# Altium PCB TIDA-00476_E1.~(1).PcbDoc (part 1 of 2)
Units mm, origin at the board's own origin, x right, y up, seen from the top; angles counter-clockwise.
Board outline 85.09 x 49.91 mm, 2 copper layers (Top Layer, Bottom Layer), stack 1.575 mm thick; 132 components, 75 nets, 329 pads, 292 vias.
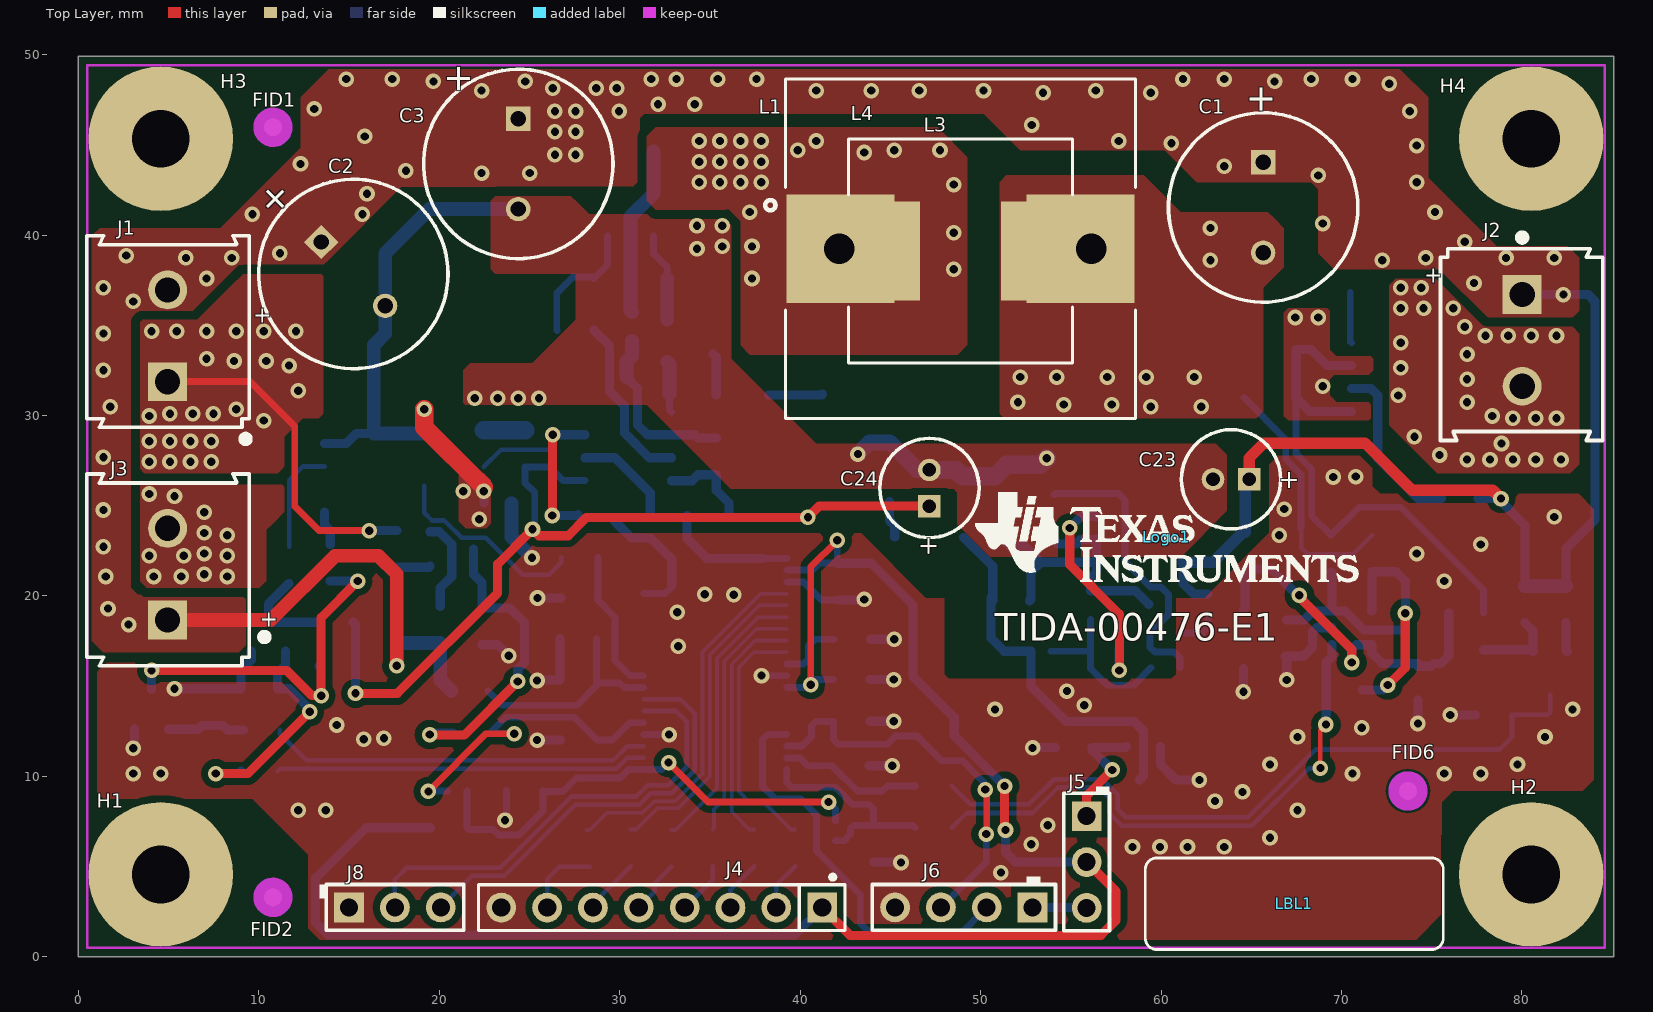
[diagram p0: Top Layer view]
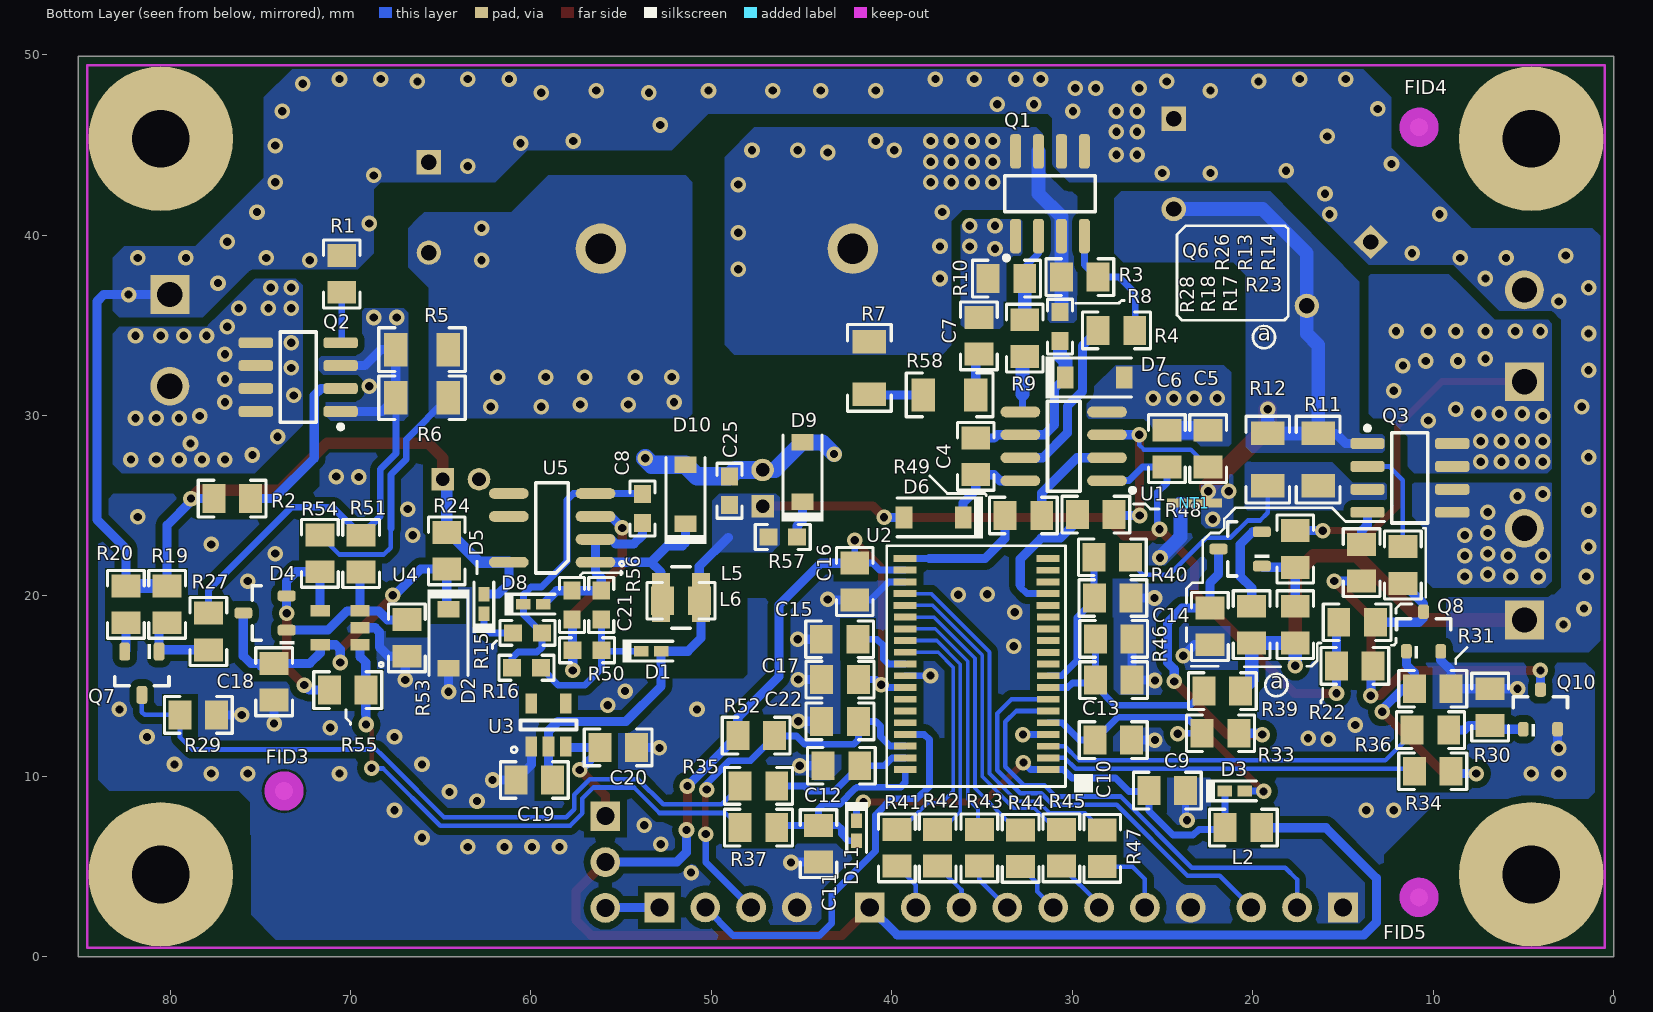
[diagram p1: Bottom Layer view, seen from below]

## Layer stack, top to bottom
Top Solder: solder mask 0.0102, Solder Resist, Dk 3.5
Top Layer: signal copper 0.0356
Dielectric1: core 1.5037, FR-4, Dk 4.8
Bottom Layer: signal copper 0.0356
Bottom Solder: solder mask 0.0102, Solder Resist, Dk 3.5

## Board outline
0,0 0,49.911 85.09,49.911 85.09,0

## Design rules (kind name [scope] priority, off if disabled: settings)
AcuteAngle [All] p1: minimum=4.50000000000000E+0001 checktracksonly=TRUE
AssemblyTestPointUsage [All] p1: valid=2
Clearance Clearance_keepout [InPolygon vs IsKeepOut] p1: gap=0.127
Clearance Clearance_poly-poly [InPolygon vs InPolygon] p2: gap=0.508
Clearance "VIA to SMD" [IsVia vs IsPad] p3: gap=0.203
Clearance Clearance_BoardEdge_MountingHoles [OnCopper and InComponentClass('Mounting Holes') vs IsKeepOut] p4: gap=1.016
Clearance Clearance_BoardEdge_Poly [OnCopper and InPoly vs IsKeepOut] p5: gap=0.508
Clearance Clearance_Poly [InPolygon] p6: gap=0.381
Clearance [All] p7: gap=0.2
ComponentClearance ComponentClearance_MountingHoles_FiducialMarks [InComponentClass('Mounting Holes') vs InComponentClass('FiducialMark')] p1: gap=1.016 collisioncheckmode=3 verticalgap=0.254 showdistances=FALSE
ComponentClearance ComponentClearance_Shunt [InComponentClass('Header') vs InComponentClass('Shunt')] p2: gap=0 collisioncheckmode=3 verticalgap=0 showdistances=FALSE
ComponentClearance ComponentClearance_Logo [InComponentClass('Logo')] p3: gap=0.889 collisioncheckmode=3 verticalgap=0.254 showdistances=FALSE
ComponentClearance ComponentClearance_ScrewToNut [(HasFootprint('NY PMS 440 0025 PH')) vs (HasFootprint('Keystone_1902C'))] p4: gap=0.127 collisioncheckmode=3 verticalgap=0.254 showdistances=FALSE
ComponentClearance ComponentClearance_MountingHoles [InComponentClass('Mounting Holes')] p5: gap=6.35 collisioncheckmode=3 verticalgap=2540 showdistances=FALSE
ComponentClearance ComponentClearance_SmallPassives [HasFootprint('0201*') or HasFootprint('0402*') or HasFootprint('0508') or HasFootprint('0603*') or HasFootprint('0612') or HasFootprint('0805*') or HasFootprint('0815*') or HasFootprint('0830*') or HasFootprint('1206*') or HasFootprint('1210*') or HasFootprint('1808*') or HasFootprint('1812*') or HasFootprint('1825*') or HasFootprint('2010*') or HasFootprint('2220*') or HasFootprint('2225*') or HasFootprint('2512*') or HasFootprint('2728*') or HasFootprint('3518*') vs HasFootprint('0201*') or HasFootprint('0402*') or HasFootprint('0508') or HasFootprint('0603*') or HasFootprint('0612') or HasFootprint('0805*') or HasFootprint('0815*') or HasFootprint('0830*') or HasFootprint('1206*') or HasFootprint('1210*') or HasFootprint('1808*') or HasFootprint('1812*') or HasFootprint('1825*') or HasFootprint('2010*') or HasFootprint('2220*') or HasFootprint('2225*') or HasFootprint('2512*') or HasFootprint('2728*') or HasFootprint('3518*')] p6: gap=0.508 collisioncheckmode=3 verticalgap=0.254 showdistances=FALSE
ComponentClearance ComponentClearance_THtoSMT [IsThruComponent vs IsSMTComponent] p7: gap=1.27 collisioncheckmode=3 verticalgap=0.762 showdistances=FALSE
ComponentClearance ComponentClearance_THtoTH [IsThruComponent vs IsThruComponent] p8: gap=3 collisioncheckmode=3 verticalgap=0.762 showdistances=FALSE
ComponentClearance [All] p9: gap=0.762 collisioncheckmode=3 verticalgap=0.254 showdistances=FALSE
DiffPairsRouting DiffPair_DP_DMDiffPairsRouting [InDifferentialPair ('MSP_DP_DM_DIFF')] p1: maxlimit=0.203 minlimit=0.203 mostfreqgap=0.203 toplayer_minwidth=0.381 toplayer_maxwidth=0.381 toplayer_prefwidth=0.381 bottomlayer_minwidth=0.381 bottomlayer_maxwidth=0.381 bottomlayer_prefwidth=0.381 maxuncoupledlength=12.7
DiffPairsRouting DiffPair_MSP_DP_DMDiffPairsRouting [InDifferentialPair ('MSP_DP_DM_DIFF')] p2: maxlimit=0.203 minlimit=0.203 mostfreqgap=0.203 toplayer_minwidth=0.381 toplayer_maxwidth=0.381 toplayer_prefwidth=0.381 bottomlayer_minwidth=0.381 bottomlayer_maxwidth=0.381 bottomlayer_prefwidth=0.381 maxuncoupledlength=12.7
DiffPairsRouting [All] p3: maxlimit=0.203 minlimit=0.203 mostfreqgap=0.203 toplayer_minwidth=0.381 toplayer_maxwidth=0.381 toplayer_prefwidth=0.381 bottomlayer_minwidth=0.381 bottomlayer_maxwidth=0.381 bottomlayer_prefwidth=0.381 maxuncoupledlength=25.4
FabricationTestPointUsage TestPointUsage [All] p1: valid=2 allowmultiple=FALSE
FabricationTestpoint Testpoint [All] p1: side=3 testpointundercomponent=TRUE minsize=1.016 maxsize=2.54 preferedsize=1.524 minholesize=0 maxholesize=1.016 preferedholesize=0.813 testpointgrid=0.025 allowsidetop=TRUE allowsidebottom=TRUE usegrid=TRUE gridtolerance=0
FanoutControl Fanout_LCC [IsLCC] p1: bgadir=Out bgaviamode=Centered fanoutstyle=Auto fanoutdirection=Alternating viagrid=0.025 // Fanout_LCC (Default Rule)
FanoutControl Fanout_BGA [IsBGA] p2: bgadir=Out bgaviamode=Centered fanoutstyle=Auto fanoutdirection=Alternating viagrid=0.025 // Fanout_BGA (Default Rule)
FanoutControl Fanout_Default [All] p4: bgadir=Out bgaviamode=Centered fanoutstyle=Auto fanoutdirection=Alternating viagrid=0.025 // Fanout_Default (Default Rule)
FanoutControl Fanout_Small [(CompPinCount < 5)] p5: bgadir=Out bgaviamode=Centered fanoutstyle=Auto fanoutdirection=OutThenIn viagrid=0.025 // Fanout_Small (Default Rule)
HoleSize [All] p1: absolutevalues=TRUE maxlimit=6.375 minlimit=0.2 maxpercent=80.000 minpercent=20.000
MatchedLengths DiffPair_DP_DMMatchedLengths [InDifferentialPair ('MSP_DP_DM_DIFF')] p1: tolerance=5.08 checknetsindiffpair=TRUE checkdiffpairvsdiffpair=TRUE checkothers=TRUE
MatchedLengths DiffPair_MSP_DP_DMMatchedLengths [InDifferentialPair ('MSP_DP_DM_DIFF')] p2: tolerance=5.08 checknetsindiffpair=TRUE checkdiffpairvsdiffpair=TRUE checkothers=TRUE
MinimumAnnularRing MinimumAnnularRing_ThermalPadVias [IsVia and InAnyComponent] p1: minimumring=0.15
MinimumAnnularRing [All] p2: minimumring=0.152
MinimumSolderMaskSliver MinimumSolderMaskSliver_Logo [InComponentClass('Logo') vs InComponentClass('Logo')] p1: minsoldermaskwidth=0.018
MinimumSolderMaskSliver [All] p2: minsoldermaskwidth=0.064
PlaneConnect [All] p1: planeconnectstyle=Direct reliefexpansion=0.254 reliefentries=4 reliefconductorwidth=0.254 reliefairgap=0.254
PolygonConnect [All] p1: connectstyle=Direct reliefconductorwidth=0.254 reliefentries=4 polygonreliefangle="90 Angle" airgapwidth=0.254
RoutingVias RoutingVias_1 [All] p1: holewidth=0.305 width=0.61 viastyle="Through Hole" minholewidth=0.305 minwidth=0.61 maxholewidth=0.457 maxwidth=0.864
RoutingVias ThermalPadVias [IsVia and InAnyComponent] p2: holewidth=0.305 width=0.61 viastyle="Through Hole" minholewidth=0.2 minwidth=0.5 maxholewidth=0.406 maxwidth=0.813
RoutingVias RoutingVias_power [InNetClass('Power')] p3: holewidth=0.305 width=0.61 viastyle="Through Hole" minholewidth=0.305 minwidth=0.61 maxholewidth=0.457 maxwidth=0.864
SilkToSilkClearance SilkToSilkClearance_Pb-FreeLogo [(HasFootprint('Pb-Free_Overlay_Medium') OR HasFootprint('Pb-Free_Overlay_Small')) vs (HasFootprint('Pb-Free_Overlay_Medium') OR HasFootprint('Pb-Free_Overlay_Small'))] p1: silktosilkclearance=0
SilkToSilkClearance [All] p2: silktosilkclearance=0.127
SilkToSolderMaskClearance "Silk to Solder Mask Opening" [IsPad] p1: minsilkscreentomaskgap=0.025 clearancetoexposedcopper=TRUE
SolderMaskExpansion [All] p1: expansion=0.064
UnpouredPolygon [All] p1: allowunpoured=FALSE
Width Width_PWR [InNetClass('Power')] p1: maxlimit=2.54 minlimit=0.203 preferedwidth=0.508
Width [All] p2: maxlimit=2.54 minlimit=0.203 preferedwidth=0.381 checkconnectedcopper=TRUE
15 further rules are at their usual default settings.

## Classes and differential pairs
component class TIDA-00476_Sheet2: C1 C2 C3 C4 C5 C6 C7 C8 C21 C23 C24 C25 D1 D2 D5 D6 D7 D8 D9 D10 J1 J2 J3 L1 L3 L4 L5 L6 NT1 Q1 Q2 Q3 Q6 Q7 Q8 Q10 R1 R2 R3 R4 R5 R6 R7 R8 R9 R10 R11 R12 R13 R14 R15 R16 R17 R18 R19 R20 R22 R23 R24 R26 R27 R28 R29 R30 R31 R50 R56 R57 R58 U1 U5
component class TIDA-00467_Sheet1: C9 C10 C11 C12 C13 C14 C15 C16 C17 C18 C19 C20 C22 D3 D4 D11 J4 J5 J6 J8 L2 R33 R34 R35 R36 R37 R39 R40 R41 R42 R43 R44 R45 R46 R47 R48 R49 R51 R52 R53 R54 R55 U2 U3 U4
component class Hardware: FID1 FID2 FID3 FID4 FID5 FID6 H1 H2 H3 H4 LBL1 Logo1 ZZ1 ZZ2 ZZ3 ZZ4

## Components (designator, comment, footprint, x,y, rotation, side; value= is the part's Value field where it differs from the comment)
C1 "EKYB630ELL391MJ30S" KZN_1000x2000 65.659,41.529 r270 top
C2 "EKYB630ELL391MJ30S" KZN_1000x2000 15.24,37.846 r315 top
C3 "EKYB630ELL391MJ30S" KZN_1000x2000 24.384,43.942 r270 top
C4 "08053C104KAT2A" 0805_HV#1 35.357,27.737 r90 bottom
C5 "GRM2165C2A221JA01D" 0805_HV#1 22.479,28.169 r90 bottom
C6 "08055C105KAT2A" 0805_HV#1 24.765,28.169 r90 bottom
C7 "GRM2195C2A102JA01D" 0805_HV#1 35.179,34.417 r90 bottom
C8 "C1608X5R1A106M" 0603 53.823,24.841 r270 bottom
C9 "08055C105KAT2A" 0805_HV#1 24.74,9.22 r180 bottom
C10 "08053C104KAT2A" 0805_HV#1 27.737,12.014 r180 bottom
C11 "08055C222KAT2A" 0805_HV#1 44.069,6.274 r270 bottom
C12 "08053C104KAT2A" 0805_HV#1 42.799,10.592 r0 bottom
C13 "08055C222KAT2A" 0805_HV#1 27.711,15.342 r180 bottom
C14 "08053C104KAT2A" 0805_HV#1 27.762,19.888 r180 bottom
C15 "08055C105KAT2A" 0805_HV#1 42.901,17.602 r0 bottom
C16 "08055C105KAT2A" 0805_HV#1 42.062,20.803 r270 bottom
C17 "08055C105KAT2A" 0805_HV#1 42.875,15.367 r0 bottom
C18 "08055C105KAT2A" 0805_HV#1 74.234,15.247 r270 bottom
C19 "08055C105KAT2A" 0805_HV#1 59.817,9.804 r0 bottom
C20 "08055C105KAT2A" 0805_HV#1 55.169,11.608 r180 bottom
C21 "0603YC104JAT2A" 0603 56.109,19.495 r90 bottom
C22 "08055C102KAT2A" 0805_HV#1 42.875,13.056 r0 bottom
C23 "35ZLJ47MTA5X11" ZLJ_500x1100 63.881,26.467 r180 top
C24 "16PX100MEFCTA5X11" ZLJ_500x1100 47.168,25.984 r90 top
C25 "06033C101KAT2A" 0603 48.997,25.832 r90 bottom
D1 "1N4148X-TP" SOD-523 53.34,16.942 r180 bottom
D2 "MMSZ4715-V" SOD-123 64.567,17.628 r270 bottom
D3 "BAS 52-02V H6327" SOD-523 21.006,9.195 r180 bottom
D4 "BAS70-05-7-F" SOT-23 74.742,19.057 r0 bottom
D5 "1N4148X-TP" SOD-523 62.611,19.558 r90 bottom
D6 "MBR0580-TP" SOD-123 37.694,24.359 r0 bottom
D7 "MBR0580-TP" SOD-123 28.753,32.106 r180 bottom
D8 "5.61V" SOD-523 59.868,19.545 r180 bottom
D9 "MMSZ4696-V" SOD-123 44.958,26.873 r90 bottom
D10 "MBR0580-TP" SOD-123 51.435,25.629 r90 bottom
D11 "BAS 52-02V H6327" SOD-523 41.961,6.985 r270 bottom
FID1 "Fiducial" Fiducial10-20 10.795,45.974 r90 top
FID2 "Fiducial" Fiducial10-20 10.795,3.302 r90 top
FID3 "Fiducial" Fiducial10-20 73.685,9.195 r90 bottom
FID4 "Fiducial" Fiducial10-20 10.795,45.974 r90 bottom
FID5 "Fiducial" Fiducial10-20 10.795,3.302 r90 bottom
FID6 "Fiducial" Fiducial10-20 73.685,9.195 r0 top
H1 "NY PMS 440 0025 PH" "NY PMS 440 0025 PH" 4.572,4.572 r0 top
H2 "NY PMS 440 0025 PH" "NY PMS 440 0025 PH" 80.518,4.572 r0 top
H3 "NY PMS 440 0025 PH" "NY PMS 440 0025 PH" 4.572,45.339 r0 top
H4 "NY PMS 440 0025 PH" "NY PMS 440 0025 PH" 80.518,45.339 r0 top
J1 "282841-2" TEC_282841-2 4.953,34.417 r90 top
J2 "282841-2" TEC_282841-2 80.01,34.163 r270 top
J3 "282841-2" TEC_282841-2 4.953,21.209 r90 top
J4 "TSW-108-07-G-S" TSW-108-07-G-S 32.334,2.735 r180 top
J5 "5-146278-3" TE_5-146278-3 55.88,5.258 r270 top
J6 "5-146278-4" TE_5-146278-4 49.073,2.743 r180 top
J8 "5-146278-3" TE_5-146278-3 17.551,2.743 r0 top
L1 "74435574700" WE-HCB_1890 48.895,39.243 r0 top
L2 "MMZ2012R300A" 0805_HV#1 20.523,7.163 r0 bottom
L3 "MSS1278-223MLB" mss1278 48.895,39.116 r0 top
L4 "22uH" IND_550MIL_TH 49.149,39.243 r0 top
L5 "100uH" SRN3015 51.689,19.914 r180 bottom
L6 "47uH" 0805_HV#1 51.689,19.736 r180 bottom
LBL1 "Size: 0.65\" x 0.20 \"" Label_650x200 67.386,2.946 r0 top
Logo1 "Texas Instruments" TI_Stacked_Overlay_Small 60.325,23.266 r0 top
NT1 "Net-Tie" Net-Tie_20milWide_60milLong 23.241,25.146 r180 bottom net-tie
Q1 "CSD88539ND" SO-8L 31.242,42.291 r90 bottom
Q2 "CSD88539ND" SO-8L 72.898,32.131 r0 bottom
Q3 "CSD88539ND" SO-8L 11.303,26.543 r180 bottom
Q6 "BC856B-7-F" SOT-23 20.701,22.606 r0 bottom
Q7 "BC856B-7-F" SOT-23 81.559,15.723 r270 bottom
Q8 "MMBT3904" SOT-23L 10.541,18.034 r90 bottom
Q10 "MMBT3904" SOT-23L 4.064,13.716 r90 bottom
R1 "CRCW08052K05FKEA" 0805_HV#1 70.485,37.846 r90 bottom
R2 "CRCW08052K05FKEA" 0805_HV#1 76.556,25.4 r0 bottom
R3 "CRCW080533K2FKEA" 0805_HV#1 29.591,37.668 r180 bottom
R4 "RC0805JR-075R1L" 0805_HV#1 27.559,34.722 r180 bottom
R5 "CSR1206FK20L0" 1206 66.04,33.655 r0 bottom
R6 "CSR1206FK20L0" 1206 66.04,30.988 r0 bottom
R7 "CRCW120610R0JNEA" 1206 41.25,32.639 r90 bottom
R8 "CRCW06035R10JNEA" 0603 30.683,34.925 r90 bottom
R9 "CRCW080510R0FKEA" 0805_HV#1 32.639,34.29 r270 bottom
R10 "CRCW080533K2FKEA" 0805_HV#1 33.655,37.592 r180 bottom
R11 "CSR1206FKR750" 1206 16.383,27.559 r90 bottom
R12 "CSR1206FKR750" 1206 19.177,27.559 r90 bottom
R13 "CRCW08052K05FKEA" 0805_HV#1 13.97,21.844 r90 bottom
R14 "CRCW08052K05FKEA" 0805_HV#1 11.684,21.717 r90 bottom
R15 "CRCW0603100KJNEA" 0603 60.198,17.958 r0 bottom
R16 "CRCW06032K20JNEA" 0603 60.249,16.027 r180 bottom
R17 "CRCW0805100KFKEA" 0805_HV#2 35.179,41.91 r270 bottom
R18 "CRCW080542K2FKEA" 0805_HV#1 20.066,18.415 r270 bottom
R19 "CRCW0805100KFKEA" 0805_HV#1 80.162,19.533 r90 bottom
R20 "CRCW080542K2FKEA" 0805_HV#1 82.448,19.533 r90 bottom
R22 "CRCW080533K2FKEA" 0805_HV#1 14.351,16.129 r0 bottom
R23 "CRCW080533K2FKEA" 0805_HV#1 14.224,18.542 r0 bottom
R24 "ERJ-6ENF2492V" 0805_HV#1 64.668,22.504 r90 bottom
R26 "CRCW0805100KFKEA" 0805_HV#1 17.653,22.606 r270 bottom
R27 "CRCW0805100KFKEA" 0805_HV#1 77.876,18.034 r270 bottom
R28 "CRCW08054K70JNEA" 0805_HV#1 22.377,18.313 r90 bottom
R29 "CRCW08057K68FKEA" 0805_HV#1 78.435,13.411 r0 bottom
R30 "CRCW080533K2FKEA" 0805_HV#1 6.858,13.843 r270 bottom
R31 "CRCW080533K2FKEA" 0805_HV#3 6.731,7.112 r90 bottom
R33 "CRCW0805205RFKEA" 0805_HV#1 21.793,12.395 r0 bottom
R34 "CRCW08057K68FKEA" 0805_HV#1 10.033,10.287 r0 bottom
R35 "CRCW0805205RFKEA" 0805_HV#1 47.396,9.474 r180 bottom
R36 "CRCW08057K68FKEA" 0805_HV#1 10.16,12.573 r0 bottom
R37 "CRCW080510K0JNEA" 0805_HV#1 47.396,7.163 r0 bottom
R39 "CRCW0805200KFKEA" 0805_HV#1 21.692,14.732 r0 bottom
R40 "CRCW0805205RFKEA" 0805_HV#1 27.788,22.149 r0 bottom
R41 "CRCW08052K05FKEA" 0805_HV#1 39.726,6.045 r270 bottom
R42 "CRCW08052K05FKEA" 0805_HV#1 37.465,6.045 r270 bottom
R43 "CRCW08052K05FKEA" 0805_HV#1 35.154,6.045 r270 bottom
R44 "CRCW08052K05FKEA" 0805_HV#1 32.868,6.02 r270 bottom
R45 "CRCW08052K05FKEA" 0805_HV#1 30.607,6.045 r270 bottom
R46 "CRCW08059K53FKEA" 0805_HV#1 27.711,17.628 r0 bottom
R47 "CRCW08052K05FKEA" 0805_HV#1 28.346,6.02 r270 bottom
R48 "CRCW0805205RFKEA" 0805_HV#1 28.702,24.511 r0 bottom
R49 "CRCW0805205RFKEA" 0805_HV#1 32.715,24.46 r0 bottom
R50 "CRCW0603100KJNEA" 0603 56.896,16.993 r0 bottom
R51 "RT0805BRD074K02L" 0805_HV#1 69.418,22.352 r270 bottom
R52 "CRCW08052K05FKEA" 0805_HV#1 47.523,12.268 r180 bottom
R53 "RT0805BRD07169KL" 0805_HV#1 66.878,17.678 r90 bottom
R54 "RT0805BRD074K02L" 0805_HV#1 71.694,22.359 r270 bottom
R55 "RT0805BRD07169KL" 0805_HV#1 70.155,14.783 r180 bottom
R56 "CRCW060312K0JNEA" 0603 57.734,19.495 r270 bottom
R57 "CRCW0603200RJNEA" 0603 46.05,23.266 r0 bottom
R58 "CRCW120610R0JNEA" 1206 36.805,31.14 r0 bottom
U1 "LM5109A" M08A_N 30.48,28.296 r0 bottom
U2 "MSP430F5132IDAR" DA_38P 35.306,16.104 r0 bottom
U3 "TLV70433DBVR" DBV0005A_N 59.03,12.852 r90 bottom
U4 "OPA170AIDBV" SOT23-5P 70.612,18.237 r0 bottom
U5 "UCC28880DR" D0007A_N 58.826,23.774 r0 bottom
ZZ1 "This Assembly Note is for PCB labels only" AssemblyNoteLabel 14.554,75.692 r0 top
ZZ2 "These assemblies are ESD sensitive, ESD precautions shall be observed." AssemblyNote 14.554,72.926 r0 top
ZZ3 "These assemblies must be clean and free from flux and all contaminants. Use of no clean flux is not acceptable." AssemblyNote 14.554,70.677 r0 top
ZZ4 "These assemblies must comply with workmanship standards IPC-A-610 Class 2, unless otherwise specified." AssemblyNote 14.554,68.428 r0 top

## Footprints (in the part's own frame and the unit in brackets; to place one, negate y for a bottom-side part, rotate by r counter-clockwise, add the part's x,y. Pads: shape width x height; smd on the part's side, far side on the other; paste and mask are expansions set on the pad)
0603 [mm] "0603 from SM-752 data"
  rect 1x0.95 smd: 1(-0.8,0) 2(0.8,0)
  silkscreen extent -1.52,-0.69 1.52,0.69, body extent -0.87,-0.47 0.87,0.47, height 0.85
0805_HV#1 [mil] "0805 with 30mil clearance between pads"
  rect 50x63 smd: 1(-40,0) 2(40,0)
  silkscreen extent -74,-40 74,40, body extent -43,-29 43,29, height 43
0805_HV#2 [mil] "0805 with 30mil clearance between pads"
  rect 50x63 smd: 1(885,690) 2(965,690)
  silkscreen extent 851,650 999,730, body extent 882,661 968,719, height 43
0805_HV#3 [mil] "0805 with 30mil clearance between pads"
  rect 63x50 smd: 1(305,90) 2(305,170)
  silkscreen extent 265,56 345,204, body extent 276,87 334,173, height 43
1206 [mm] "1206 from SM-752 data"
  rect 1.3x1.85 smd: 1(-1.45,0) 2(1.45,0)
  silkscreen extent -2.4,-1.21 2.4,1.21, body extent -1.7,-0.9 1.7,0.9, height 1.35
AssemblyNote [mm] "Assembly Note"
AssemblyNoteLabel [mm] "Assembly Note for PCB Labels"
D0007A_N [mm] "SOIC, 7-Leads, Body 4.9x3.9mm, Pitch 1.27mm, IPC Medium Density"
  oval 2.2x0.6 smd: 1(-2.4,1.905) 2(-2.4,0.635) 3(-2.4,-0.635) 4(-2.4,-1.905) 5(2.4,-1.905) 6(2.4,-0.635) 8(2.4,1.905)
  silkscreen extent -0.9,-2.5 0.9,2.5, body extent -3,-2.5 3,2.5, height 1.54
DA_38P [mil]
  rect 50x15 smd: 1(-156.2,225.5) 2(-156.2,199.9) 3(-156.2,174.3) 4(-156.2,148.7) 5(-156.2,123.1) 6(-156.2,97.5) 7(-156.2,71.9) 8(-156.2,46.3) 9(-156.2,20.7) 10(-156.2,-4.9) 11(-156.2,-30.5) 12(-156.2,-56.1) 13(-156.2,-81.7) 14(-156.2,-107.3) 15(-156.1,-132.9) 16(-156.1,-158.5) 17(-156.1,-184.1) 18(-156.1,-209.7) 19(-156.1,-235.3) 20(155.9,-235.4) 21(155.9,-209.8) 22(155.9,-184.2) 23(155.9,-158.6) 24(155.9,-133) 25(155.8,-107.4) 26(155.8,-81.8) 27(155.8,-56.2) 28(155.8,-30.6) 29(155.8,-5) 30(155.8,20.6) 31(155.8,46.2) 32(155.8,71.8) 33(155.8,97.4) 34(155.8,123) 35(155.8,148.6) 36(155.8,174.2) 37(155.8,199.8) 38(155.8,225.5)
  silkscreen extent -253,235 -213,275
DBV0005A_N [mm] "SOT23, 5-Leads, Body 2.9x1.6mm, Pitch 0.95mm, Lead Span 2.8mm, IPC Medium Density"
  rect 1.1x0.65 smd: 1(-1.2,0.95) 2(-1.2,0) 3(-1.2,-0.95) 4(1.2,-0.95) 5(1.2,0.95)
  silkscreen extent -0.25,-1.55 0.25,1.55, body extent -1.42,-1.46 1.42,1.46, height 1.08
Fiducial10-20 [mm]
  round 1 smd mask+0.5: 1(0,0)
  Top Layer keep-out circle w1.178: c0,0 r0.5
IND_550MIL_TH [mil] "WURTH ELEKTRONIK"
  round 110 hole 67: 1(-275,0) 2(275,0)
KZN_1000x2000 [mm] "TH, 2-Leads, Dia 10mm, Pin Spacing 5mm"
  rect 1.35x1.35 hole 0.85: 1(-2.5,0)
  round 1.35 hole 0.85: 2(2.5,0)
  silkscreen extent -5.25,-5.25 5.25,5.25, body extent -5.26,-5.26 5.26,5.26, height 21.5
Label_650x200 [mil] "Thermal Transfer Label"
  round 1 on Mech13: 0(0,0)
  silkscreen extent -325,-100 325,100, body extent -326,-101 326,101, height 1
M08A_N [mm] "SOIC, 8-Leads, Body 4.9x3.9mm, Pitch 1.27mm, IPC Medium Density"
  oval 2.2x0.6 smd: 1(-2.4,1.905) 2(-2.4,0.635) 3(-2.4,-0.635) 4(-2.4,-1.905) 5(2.4,-1.905) 6(2.4,-0.635) 7(2.4,0.635) 8(2.4,1.905)
  silkscreen extent -3.93,-2.5 0.9,2.56, body extent -2,-2.5 2,2.5, height 1.75
mss1278 [mm] "Coilcraft recommended land pattern.  Document 598-2 rev 04/04/13"
  rect 4x5.5 smd: 1(-4.25,0) 2(4.25,0)
  silkscreen extent -6.2,-6.2 6.2,6.2, body extent -6.15,-6.15 6.15,6.15, height 8.05
Net-Tie_20milWide_60milLong [mil] "20mil net tie, no solder mask opening, no solder paste"
  rect 60x20 smd paste-10 mask-10: 1(-30,0) 2(30,0)
"NY PMS 440 0025 PH" [mm] "4-40 nylon screw and mounting hole"
  round 8 hole 3.2: 1(0,0)
  body extent -3.3,-3.3 3.3,3.3, height 2.69
SO-8L [mm] "SOIC, 8-Leads, Body 5.0x4.0mm (max), Pitch 1.27mm, IPC Most Density"
  rrect50% 1.9x0.6 smd: 1(-2.35,1.905) 2(-2.35,0.635) 3(-2.35,-0.635) 4(-2.35,-1.905) 5(2.35,-1.905) 6(2.35,-0.635) 7(2.35,0.635) 8(2.35,1.905)
  silkscreen extent -3.68,-2.5 1,2.54, body extent -3,-2.45 3,2.45, height 1.59
SOD-123 [mm] "On Semi recommended land pattern"
  rect 0.915x1.22 smd: 1(-1.637,0) 2(1.637,0)
  silkscreen extent -2.74,-1.17 2.03,1.17, body extent -1.93,-0.9 1.93,0.9, height 1.35
SOD-523 [mm] "NXP Semiconductor recommended land pattern, nominal STEP model"
  rect 0.8x0.6 smd: 1(-0.55,0) 2(0.55,0)
  silkscreen extent -1.6,-0.63 1.2,0.64, body extent -0.8,-0.4 0.8,0.4, height 0.72
SOT23-5P [mil]
  rect 42x25 smd: 1(-45,37) 2(-45,0) 3(-45,-37) 4(42,-37) 5(42,37)
SOT-23 [mm] "SOT23, 3-Leads, Body 2.9x1.3mm, Pitch 0.95mm, Lead Span 2.5mm, IPC Medium Density"
  rrect50% 1x0.6 smd: 1(-1.2,0.95) 2(-1.2,-0.95) 3(1.2,0)
  silkscreen extent -1.63,-1.5 0.7,1.76, body extent -1.16,-1.45 1.21,1.45, height 1
SOT-23L [mm] "SOT23, 3-Leads, Body 2.9x1.3mm, Pitch 0.95mm, Lead Span 2.5mm, IPC High Density"
  rrect50% 0.8x0.6 smd: 1(-1.1,0.95) 2(-1.1,-0.95) 3(1.1,0)
  silkscreen extent -1.5,-1.5 0.7,1.5, body extent -1.16,-1.45 1.21,1.45, height 1
SRN3015 [mm] "SMD, 2-Leads, Body 3x3mm"
  rect 1x2.7 smd: 1(-1.1,0) 2(1.1,0)
  silkscreen extent -0.5,-1.7 0.5,1.7
TE_5-146278-3 [mm] "TE CONNECTIVITY"
  rect 1.65x1.65 hole 1: 1(-2.54,0)
  round 1.65 hole 1: 2(0,0) 3(2.54,0)
  silkscreen extent -4.19,-1.27 3.81,1.27, body extent -3.68,-1.17 3.68,1.17, height 8.13
TE_5-146278-4 [mm] "TE CONNECTIVITY"
  rect 1.65x1.65 hole 1: 1(-3.81,0)
  round 1.65 hole 1: 2(-1.27,0) 3(1.27,0) 4(3.81,0)
  silkscreen extent -5.08,-1.73 5.08,1.27, body extent -4.95,-1.17 4.95,1.17, height 8.13
TEC_282841-2 [mm] "TE Connectivity"
  rect 2.15x2.15 hole 1.4: 1(-2.54,0)
  round 2.15 hole 1.4: 2(2.54,0)
  silkscreen extent -5.91,-4.53 5.55,4.48, body extent -5.08,-4.52 5.58,4.48, height 15.2
TI_Stacked_Overlay_Small [mm]
  silkscreen extent -10.63,-2.49 10.63,2.49
TSW-108-07-G-S [mm] "Samtec 100mil, 1x8, 230 mil above insulator"
  rect 1.65x1.65 hole 1.016: 1(-8.89,0)
  round 1.65 hole 1.016: 2(-6.35,0) 3(-3.81,0) 4(-1.27,0) 5(1.27,0) 6(3.81,0) 7(6.35,0) 8(8.89,0)
  silkscreen extent -10.16,-1.81 10.16,1.27, body extent -10.16,-1.27 10.16,1.27, height 8.38
WE-HCB_1890 [mm] "WURTH ELEKTRONIK"
  rect 6x6 smd: 1(-6.65,0) 2(6.65,0)
  silkscreen extent -9.7,-9.4 9.7,9.4, body extent -9.65,-9.35 9.65,9.35, height 9.2
ZLJ_500x1100 [mm] "TH, 2-Leads, Dia 5mm,  Lead Spacing 2mm"
  rect 1.25x1.25 hole 0.75: 1(-1,0)
  round 1.25 hole 0.75: 2(1,0)
  silkscreen extent -2.75,-2.75 2.75,2.75, body extent -2.73,-2.75 2.75,2.75, height 12.51

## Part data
C1: library part EKZN350ELL471MJ20S, "CAP, AL,390 µF, 63 V, +/- 20%, 0.043 ohm, TH"
C2 C3: library part EKZN350ELL471MJ20S, "CAP, AL, 470 µF, 35 V, +/- 20%, 0.028 ohm, TH"
C4 C10 C12 C14: "CAP, CERM, 0.1uF, 25V, +/-10%, X7R, 0805"
C5: "CAP, CERM, 220 pF, 100 V, +/- 5%, C0G/NP0, 0805"
C6 C9 C15 C16 C17 C18 C19 C20: "CAP, CERM, 1uF, 50V, +/-10%, X7R, 0805"
C7: "CAP, CERM, 1000 pF, 100 V, +/- 5%, C0G/NP0, 0805"
C8: "CAP, CERM, 10 µF, 10 V, +/- 20%, X5R, 0603"
C11 C13: "CAP, CERM, 2200 pF, 50 V, +/- 10%, X7R, 0805"
C21: "CAP, CERM, 0.1 µF, 16 V, +/- 5%, X7R, 0603"
C22: "CAP, CERM, 1000 pF, 50 V, +/- 10%, X7R, 0805"
C23: "CAP, AL, 47 µF, 35 V, +/- 20%, 0.4 ohm, TH"
C24: library part 35ZLJ47MTA5X11, "CAP, AL, 100 µF, 16 V, +/- 20%, 0.4 ohm, TH"
C25: "CAP, CERM, 100 pF, 25 V, +/- 10%, X7R, 0603"
D1 D5: "Diode, Switching, 75 V, 0.3 A, SOD-523"
D2: "Diode, Zener, 36 V, 500 mW, SOD-123"
D3 D11: "Diode, Schottky, 45 V, 0.75 A, SOD-523"
D4: "Diode, Schottky, 70 V, 0.07 A, SOT-23"
D6 D7 D10: "Diode, Schottky, 80 V, 0.5 A, SOD-123"
D8: library part MM5Z5V6ST1G, "Diode, Zener, 5.61 V, 500 mW, SOD-523"
D9: "Diode, Zener, 9.1 V, 500 mW, SOD-123"
FID1 FID2 FID3 FID4 FID5 FID6: "Fiducial mark.  There is nothing to buy or mount."
H1 H2 H3 H4: "Machine Screw, Round, #4-40 x 1/4, Nylon, Philips panhead"
J1 J2 J3: "Terminal Block, 2x1, 5.08mm, TH"
J4: "Header, TH, 100mil, 8x1, Gold plated, 230 mil above insulator"
J5 J8: "Header, 100mil, 3x1, Tin, TH"
J6: "Header, 100mil, 4x1, Tin, TH"
L1: "Inductor, Shielded Drum Core, Ferrite, 47 µH, 6.8 A, 0.0335 ohm, SMD"
L2: "Ferrite Bead, 30 ohm @ 100MHz, 1.5A, 0805"
L3: "Inductor, Shielded Drum Core, Ferrite, 22 µH, 4 A, 0.04 ohm, SMD"
L4: library part 74435572200, "Inductor, Shielded Drum Core, Ferrite, 22 µH, 11 A, 0.0146 ohm, SMD"
L5: library part SRN3015-1R0Y, "Inductor, Drum Core, Ferrite, 100 µH, 0.4 A, 1.596 ohm, SMD"
L6: library part SRN3015-1R0Y, "Inductor, Drum Core, Ferrite, 47 µH, 0.4 A, 1.4 ohm, SMD"
LBL1: library part THT-14-423-10, "Thermal Transfer Printable Labels, 0.650\" W x 0.200\" H - 10,000 per roll"
Logo1: library part TI_Logo, "Texas Instrument Corporate Signature"
NT1: "Single point connection between nets."
Q1 Q2 Q3: "MOSFET, N-CH, 60V, 6.3A, SO-8"
Q6 Q7: library part "BC856B-7-F, Diodes Inc.", "Transistor, PNP, 65 V, 0.1 A, SOT-23"
Q8 Q10: library part "MMBT3904, Fairchild Semiconductor", "Transistor, NPN, 40V, 0.2A, SOT-23"
R1 R2 R13 R14 R41 R42 R43 R44 R45 R47 R52: "RES, 2.05k ohm, 1%, 0.125W, 0805"
R3 R10 R22 R23 R30 R31: "RES, 33.2k ohm, 1%, 0.125W, 0805"
R4: "RES, 5.1, 5%, 0.125 W, 0805"
R5 R6: "RES, 0.02, 1%, 0.5 W, 1206"
R7 R58: "RES, 10, 5%, 0.25 W, 1206"
R8: "RES, 5.1, 5%, 0.1 W, 0603"
R9: "RES, 10.0 ohm, 1%, 0.125W, 0805"
R11 R12: "RES, 0.75, 1%, 0.5 W, 1206"
R15 R50: "RES, 100 k, 5%, 0.1 W, 0603"
R16: "RES, 2.2 k, 5%, 0.1 W, 0603"
R17 R19 R26 R27: "RES, 100k ohm, 1%, 0.125W, 0805"
R18 R20: "RES, 42.2 k, 1%, 0.125 W, 0805"
R24: "RES, 24.9 k, 1%, 0.125 W, 0805"
R28: "RES, 4.7 k, 5%, 0.125 W, 0805"
R29 R34 R36: "RES, 7.68 k, 1%, 0.125 W, 0805"
R33 R35 R40 R48 R49: "RES, 205 ohm, 1%, 0.125W, 0805"
R37: "RES, 10k ohm, 5%, 0.125W, 0805"
R39: "RES, 200 k, 1%, 0.125 W, 0805"
R46: "RES, 9.53 k, 1%, 0.125 W, 0805"
R51 R54: "RES, 4.02 k, 0.1%, 0.125 W, 0805"
R53 R55: "RES, 169 k, 0.1%, 0.125 W, 0805"
R56: "RES, 12 k, 5%, 0.1 W, 0603"
R57: "RES, 200, 5%, 0.1 W, 0603"
U1: library part LM5109AMAX/NOPB, "High Voltage 1A Peak Half Bridge Gate Driver, 8-pin Narrow SOIC, Pb-Free"
U2: "IC, MIXED SIGNAL MICROCONTROLLER"
U3: "Single Output LDO, 150 mA, Fixed 3.3 V Output, 2.5 to 24 V Input, with Ultra-Low IQ, 5-pin SOT-23 (DBV), -40 to 125 degC, Green (RoHS & no Sb/Br)"
U4: "IC, 36V, Single-Supply, Op Amp"
U5: "700-V Lowest Quiescent Current Off-Line Switcher, D0007A"
ZZ1: library part AssemblyNoteLabel
ZZ2 ZZ3 ZZ4: library part AssemblyNote

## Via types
v1: diameter 0.864, hole 0.457, Top Layer to Bottom Layer, 292 vias

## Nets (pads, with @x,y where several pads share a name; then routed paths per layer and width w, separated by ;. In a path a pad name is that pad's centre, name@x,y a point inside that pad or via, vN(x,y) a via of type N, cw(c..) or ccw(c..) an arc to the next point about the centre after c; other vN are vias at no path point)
B-: Q2.1 Q2.3 R5.2 R6.2 R27.1 R51.1 | length 30.2
  Bottom Layer w0.381: R6.2@67.49,30.988 67.49,27.887 68.351,27.026 68.351,24.435 R51.1@69.418,23.368 70.968,24.917 73.304,24.917 77.876,20.345 R27.1@77.876,19.05
  Bottom Layer w0.508: Q2.1@70.548,30.226 68.252,30.226 R6.2@67.49,30.988 R5.2@67.49,33.655 68.326,33.655 69.215,32.766 Q2.3@70.548,32.766
  other v1: 68.961,31.623 67.437,35.433 68.707,35.433
B_I: R37.2 R55.2 U4.1 | length 31.1
  Top Layer w0.254: v1(68.834,10.465) 68.834,12.573 v1(69.139,12.878)
  Bottom Layer w0.254: R37.2@48.412,7.163 49.225,7.976 52.879,7.976 54.291,9.387 56.54,9.387 57.15,8.777 57.15,7.95 57.836,7.264 65.024,7.264 68.199,10.439 68.809,10.439 v1(68.834,10.465)
  Bottom Layer w0.508: v1(69.139,12.878) 69.139,13.437 69.154,13.452 69.154,16.322 69.469,16.637 U4.1@69.469,17.297
B_S: C1.2 L1.2 L3.2 L4.2 R5.1 R6.1 R54.1 | length 14.2
  Bottom Layer w0.254: 67.767,23.749 67.767,22.682 68.151,22.298 70.617,22.298 R54.1@71.694,23.375
  Bottom Layer w0.381: R6.1@64.59,30.988 66.909,28.669 66.909,27.579 67.767,26.721 67.767,23.749
  other v1: 59.436,30.48 62.23,30.48 54.61,30.607 57.277,30.607 52.07,30.734 52.197,32.131 54.229,32.131 57.023,32.131 59.182,32.131 61.849,32.131 62.738,38.608 62.738,40.386
B_V: Q7.3 R29.2 R35.1 | length 39.6
  Bottom Layer w0.254: R35.1@48.412,9.474 49.428,8.458 52.68,8.458 54.077,9.855 56.737,9.855 56.988,9.604 56.991,9.604 57.604,8.992 57.604,8.179 58.036,7.747 64.821,7.747 67.745,10.671 67.745,10.678 68.24,11.173 68.247,11.173 68.566,11.492 78.78,11.492 79.451,12.163 R29.2@79.451,13.411 81.407,13.411 81.559,13.564 Q7.3@81.559,14.523
GND: C9.2 C10.2 C11.2 C12.2 C13.2 C14.2 C15.2 C16.2 C17.2 C18.2 C19.2 C20.2 C22.2 D2.2 J4.8 J6.4 J8.1 NT1.1 Q8.2 Q10.2 R28.1 R29.1 R30.1 R31.1 R46.1 R53.1 U2.4 U2.22 U2.30 U3.1 U4.2 | length 48.2
  Bottom Layer w0.381: v1(23.647,7.569) 23.647,7.75 23.724,7.826 C9.2@23.724,9.22 ; U2.4@31.339,12.327 32.733,12.327 v1(32.741,12.319) ; v1(37.861,15.588) 37.869,15.58 U2.30@39.263,15.58 ; U2.22@39.266,20.782 40.203,20.782 41.199,19.787 C16.2@42.062,19.787
  Bottom Layer w0.508: v1(3.048,11.557) 3.114,11.623 Q10.2@3.114,12.616 ; v1(5.334,14.859) R30.1@6.858,14.859 R31.1@9.017,14.859 9.017,15.875 9.591,16.449 Q8.2@9.591,16.934 ; R28.1@22.377,17.297 23.241,17.297 v1(23.851,16.688) ; v1(25.425,12.014) C10.2@26.721,12.014 ; v1(25.425,15.316) 25.552,15.316 25.578,15.342 C13.2@26.695,15.342 R46.1@26.695,17.628 ; v1(25.451,19.888) C14.2@26.746,19.888 ; C16.2@42.062,19.787 43.358,19.787 43.383,19.812 v1(43.561,19.812) ; C12.2@43.815,10.592 v1(45.11,10.592) ; C22.2@43.891,13.056 v1(45.187,13.056) ; C17.2@43.891,15.367 v1(45.187,15.367) ; C15.2@43.917,17.602 v1(45.212,17.602) ; C11.2@44.069,5.258 45.568,5.258 v1(45.593,5.232) ; v1(52.883,11.582) 52.984,11.582 53.01,11.608 C20.2@54.153,11.608 ; U3.1@59.98,11.652 59.98,10.658 C19.2@60.833,9.804 v1(62.128,9.804) ; v1(64.567,14.695) D2.2@64.567,15.99 ; R53.1@66.878,16.662 67.894,16.662 68.402,17.17 68.402,18.009 68.631,18.237 U4.2@69.469,18.237 ; v1(66.97,15.351) R53.1@66.97,16.646 ; v1(74.234,12.936) C18.2@74.234,14.231 ; v1(76.022,13.411) R29.1@77.419,13.411
  Bottom Layer w0.762: NT1.1@24.003,25.146 24.003,23.266 v1(25.146,22.123)
  other v1: 51.13,4.674 58.42,6.096 59.944,6.096 61.468,6.096 63.5,6.096 52.807,6.248 66.04,6.604 53.721,7.29 12.192,8.128 13.716,8.128 67.564,8.128 62.992,8.636 64.516,9.144 3.048,10.16 4.572,10.16 70.612,10.16 75.692,10.16 77.724,10.16 66.04,10.668 79.756,10.668 15.824,12.065 16.942,12.116 67.564,12.192 81.28,12.192 71.12,12.7 14.326,12.852 50.8,13.716 82.804,13.716 55.753,13.945 54.788,14.732 33.249,17.221 33.198,19.101 36.322,20.066 34.722,20.091 75.692,20.828 74.168,22.352 77.724,22.86 66.548,23.368 81.788,24.384 66.827,24.816 69.545,26.594 70.79,26.619
L_EN: Q10.1 R30.2 R36.1 | length 4.3
  Bottom Layer w0.508: Q10.1@5.014,12.616 6.647,12.616 R30.2@6.858,12.827 8.026,12.827 8.28,12.573 R36.1@9.144,12.573
L_S: Q3.3 R11.1 R12.1 R40.1 | length 11.1
  Bottom Layer w0.254: R12.1@19.177,26.109 19.177,24.613 19.607,24.183 20.292,24.183 21.242,23.233 22.589,23.233 24.638,21.184 26.086,21.184 26.772,21.869 R40.1@26.772,22.149
NetC4_1: C4.1 D6.1 U1.8 | length 5.3
  Bottom Layer w0.508: U1.8@32.88,26.391 34.011,26.391 34.341,26.721 C4.1@35.357,26.721 35.357,25.857 36.056,25.158 D6.1@36.056,24.359
NetC4_2: C4.2 D7.1 R8.1 U1.6 | length 9.7
  Bottom Layer w0.508: D7.1@30.39,32.106 30.985,31.511 30.985,29.493 31.547,28.931 U1.6@32.88,28.931 34.163,28.931 34.341,28.753 C4.2@35.357,28.753
  Bottom Layer w0.762: D7.1@30.39,32.106 30.378,32.117 30.378,32.995 30.683,33.299 R8.1@30.683,34.125
NetC7_1: C7.1 R58.1 | length 2.3
  Bottom Layer w0.508: C7.1@35.179,33.401 35.355,33.225 R58.1@35.355,31.14
NetC8_1: C8.1 D8.1 R15.1 R16.1 U5.4 | length 16.5
  Bottom Layer w0.381: C8.1@54.077,25.616 54.14,25.679 U5.4@56.426,25.679 57.658,25.679 58.014,25.324 58.014,21.909 59.425,20.498 59.995,20.498 60.418,20.075 D8.1@60.418,19.545 60.418,18.978 R15.1@59.398,17.958 59.398,17.159 59.665,16.893 60.73,16.893 61.049,16.574 R16.1@61.049,16.027
NetC8_2: C8.2 C21.2 D8.2 D10.1 L5.1 L6.1 R56.1 U5.1 U5.2 | length 19
  Bottom Layer w0.508: D10.1@51.435,23.991 51.435,22.962 51.613,22.784 52.438,22.784 53.353,21.869 ; L6.1@52.705,19.736 52.789,19.82 L5.1@52.789,19.914 52.789,21.306 53.353,21.869 ; C8.2@53.823,24.041 53.823,23.368 54.305,22.885 55.093,22.885 55.096,22.889 55.306,22.889 55.557,23.139 U5.2@56.426,23.139 U5.1@56.426,21.869 ; D8.2@59.318,19.545 58.569,20.295 R56.1@57.734,20.295 C21.2@56.109,20.295 56.109,21.006 56.426,21.324 U5.1@56.426,21.869 ; 53.353,21.869 U5.1@56.426,21.869
NetC9_1: C9.1 D3.1 D11.1 L2.2 U2.1 | length 26.7
  Top Layer w0.381: v1(32.715,10.77) 34.906,8.579 v1(41.58,8.579)
  Bottom Layer w0.381: D3.1@21.556,9.195 21.539,9.178 L2.2@21.539,7.163 21.641,7.061 22.992,7.061 23.307,6.747 24.425,6.747 25.756,8.077 C9.1@25.756,9.22 25.806,9.169 26.87,9.169 27.607,9.906 30.025,9.906 30.495,10.376 U2.1@31.339,10.376 32.322,10.376 v1(32.715,10.77) ; v1@41.58,8.585 v1(41.58,8.579) 41.961,8.198 D11.1@41.961,7.535
NetC10_1: C10.1 D3.2 R33.2 U2.5 | length 18.3
  Top Layer w0.381: v1(19.406,9.169) 22.606,12.37 v1(24.155,12.37)
  Bottom Layer w0.381: v1(19.406,9.169) 19.482,9.169 19.507,9.195 D3.2@20.456,9.195 ; v1(24.155,12.37) 24.13,12.395 R33.2@22.809,12.395 23.698,13.284 27.483,13.284 C10.1@28.753,12.014 29.616,12.014 30.579,12.977 U2.5@31.339,12.977
NetC13_1: C13.1 R39.2 R46.2 U2.8 | length 12.2
  Bottom Layer w0.381: R39.2@22.708,14.732 23.495,13.945 27.635,13.945 28.727,15.037 C13.1@28.727,15.342 ; R46.2@28.727,17.628 C13.1@28.727,15.342 ; U2.8@31.339,14.928 30.259,14.928 29.997,15.189 28.88,15.189 C13.1@28.727,15.342
NetC14_1: C14.1 R40.2 U2.9 | length 8.1
  Bottom Layer w0.381: R40.2@28.804,22.149 28.804,19.914 C14.1@28.778,19.888 28.778,19.793 29.753,18.818 29.753,16.436 30.611,15.578 U2.9@31.339,15.578
NetC15_1: C15.1 U2.29 | length 3.6
  Bottom Layer w0.381: U2.29@39.263,16.231 40.183,16.231 40.462,16.51 40.462,17.247 40.818,17.602 C15.1@41.885,17.602
NetC20_1: C20.1 J5.1 U3.3 | length 6.6
  Top Layer w0.508: J5.1@55.88,7.798 55.88,8.788 ; 55.88,8.941 v1(57.302,10.363)
  Bottom Layer w0.508: v1(57.302,10.363) 57.226,10.439 57.201,10.439 56.185,11.455 C20.1@56.185,11.608 58.023,11.608 58.073,11.659 U3.3@58.08,11.652
NetC21_1: C21.1 D1.1 R16.2 R50.1 | length 9.1
  Bottom Layer w0.381: D1.1@53.89,16.942 56.045,16.942 R50.1@56.096,16.993 ; C21.1@56.109,18.695 56.096,18.682 R50.1@56.096,16.993 ; R16.2@59.449,16.027 58.474,15.053 57.032,15.053 56.096,15.989 R50.1@56.096,16.993
NetD4_1: D4.1 R51.2 R53.2 U4.3 | length 9.4
  Bottom Layer w0.508: R53.2@66.97,18.678 67.954,18.678 68.453,19.177 U4.3@69.469,19.177 ; R51.2@69.418,21.336 69.469,21.285 U4.3@69.469,19.177 ; D4.1@73.542,18.107 71.255,18.107 70.186,19.177 U4.3@69.469,19.177
NetD4_2: D4.2 R54.2 R55.1 U4.4 | length 12
  Top Layer w0.508: v1(72.568,15.062) 73.533,16.027 v1(73.533,19.05)
  Bottom Layer w0.508: R55.1@71.171,14.783 72.288,14.783 v1@72.552,15.046 ; U4.4@71.679,19.177 71.694,19.192 R54.2@71.694,21.343 73.018,21.343 73.542,20.819 D4.2@73.542,20.007 73.542,19.008 73.533,18.999 v1(73.533,19.05)
NetD5_1: D5.1 R15.2 | length 2.5
  Bottom Layer w0.381: R15.2@60.998,17.958 62.281,17.958 62.611,18.288 D5.1@62.611,19.008
NetD9_1: D9.1 R57.1 | length 2.1
  Bottom Layer w0.508: D9.1@44.958,25.236 44.958,24.186 45.25,23.894 R57.1@45.25,23.266
NetJ2_2: J2.2 Q2.5 Q2.6 Q2.7 Q2.8
  other v1: 76.962,27.559 78.232,27.559 79.502,27.559 80.772,27.559 82.169,27.559 75.438,27.813 78.867,28.448 74.041,28.829 79.502,29.845 80.772,29.845 81.915,29.845 78.359,29.972 76.962,30.734 73.152,31.115 76.962,32.004 73.279,32.639 76.962,33.401 73.279,34.036 77.978,34.417 79.248,34.417 80.518,34.417 81.915,34.417 76.835,34.925 73.279,35.941 74.549,35.941 76.2,35.941 73.279,37.084 74.422,37.084
NetJ3_2: J3.2 Q3.5 Q3.6
  other v1: 4.191,21.082 5.715,21.082 8.255,21.082 6.985,21.209 3.937,22.225 5.842,22.225 8.255,22.225 6.985,22.352 8.255,23.368 6.985,23.495 6.985,24.638 5.334,25.527 3.937,25.654
NetJ4_2: J4.2 R41.2 | length 2.7
  Bottom Layer w0.254: J4.2@38.684,2.735 38.684,3.988 R41.2@39.726,5.029
NetJ4_3: J4.3 R42.2 | length 2.8
  Bottom Layer w0.254: J4.3@36.144,2.735 36.144,3.708 R42.2@37.465,5.029
NetJ4_4: J4.4 R43.2 | length 2.9
  Bottom Layer w0.254: J4.4@33.604,2.735 35.154,4.284 R43.2@35.154,5.029
NetJ4_5: J4.5 R44.2 | length 3
  Bottom Layer w0.254: J4.5@31.064,2.735 31.953,3.624 31.953,4.089 R44.2@32.868,5.004
NetJ4_6: J4.6 R45.2 | length 3.2
  Bottom Layer w0.254: J4.6@28.524,2.735 28.524,2.946 R45.2@30.607,5.029
NetJ4_7: J4.7 R47.2 | length 4.2
  Bottom Layer w0.254: J4.7@25.984,2.735 25.984,4.318 26.67,5.004 R47.2@28.346,5.004
NetJ5_3: J5.3 J6.1 | length 3
  Bottom Layer w0.508: J6.1@52.883,2.743 55.855,2.743 J5.3@55.88,2.718
NetL1_1: L1.1 L3.1 L4.1 Q1.3 Q1.7 Q1.8 R3.1 R7.2 R8.2 | length 9.5
  Bottom Layer w0.762: R8.2@30.683,35.725 30.607,35.801 R3.1@30.607,37.668 Q1.3@30.607,39.941 30.607,41.021 31.877,42.291 Q1.7@31.877,44.641
  other v1: 37.338,37.592 48.514,38.1 37.338,39.37 48.514,40.132 37.211,41.275 48.514,42.799 34.417,42.926 35.56,42.926 36.703,42.926 37.846,42.926 34.417,44.069 35.56,44.069 36.703,44.069 37.846,44.069 43.561,44.577 39.878,44.704 45.212,44.704 47.752,44.704 34.417,45.212 35.56,45.212 36.703,45.212 37.846,45.212 40.894,45.212
NetQ1_2: Q1.2 R9.1 R10.2 | length 5
  Bottom Layer w0.381: Q1.2@31.877,39.941 31.877,38.989 32.639,38.227 R10.2@32.639,37.592
  Bottom Layer w0.762: R9.1@32.639,35.306 R10.2@32.639,37.592
NetQ1_4: Q1.4 R3.2 R4.2 | length 7.2
  Bottom Layer w0.381: R4.2@26.543,34.722 26.518,34.747 26.518,36.779 27.407,37.668 R3.2@28.575,37.668 ; R3.2@28.575,37.592 29.337,38.354 Q1.4@29.337,39.941
NetQ2_2: Q2.2 R2.1 | length 9.6
  Bottom Layer w0.508: Q2.2@70.548,31.496 71.628,31.496 72.009,31.115 72.009,27.635 74.244,25.4 R2.1@75.54,25.4
NetQ2_4: Q2.4 R1.1 | length 2.8
  Bottom Layer w0.381: R1.1@70.485,36.83 70.485,34.099 Q2.4@70.548,34.036
NetQ3_2: Q3.2 R14.2 | length 6
  Bottom Layer w0.254: R14.2@11.684,22.733 11.684,26.416 12.446,27.178 Q3.2@13.653,27.178
NetQ3_4: Q3.4 R13.2 | length 1.9
  Bottom Layer w0.508: Q3.4@13.653,24.638 13.653,23.939 13.97,23.622 R13.2@13.97,22.86
NetQ6_1: Q6.1 R17.1 R26.2 | length 4
  Bottom Layer w0.508: R17.1@17.653,19.431 R26.2@17.653,21.59 19.435,21.59 Q6.1@19.501,21.656
NetQ6_2: Q6.2 R18.1 | length 5.2
  Bottom Layer w0.508: Q6.2@19.501,23.556 20.005,23.556 20.701,22.86 20.701,21.082 20.066,20.447 R18.1@20.066,19.431
NetQ7_1: Q7.1 R19.1 R27.2 | length 4.6
  Bottom Layer w0.508: R27.2@77.876,17.018 80.514,17.018 Q7.1@80.609,16.923 80.609,18.07 R19.1@80.162,18.517
NetQ7_2: Q7.2 R20.1 | length 1.6
  Bottom Layer w0.508: R20.1@82.448,18.517 82.448,16.984 Q7.2@82.509,16.923
NetQ8_3: Q8.3 R14.1 R23.1 | length 5.2
  Bottom Layer w0.508: R14.1@11.684,20.701 10.541,19.558 Q8.3@10.541,19.134 10.541,18.796 10.795,18.542 R23.1@13.208,18.542
NetQ10_3: Q10.3 R13.1 R22.1 | length 21.5
  Top Layer w0.508: v1(4.064,15.875) 11.557,15.875 12.954,14.478 v1(13.462,14.478) 13.462,18.796 v1(15.494,20.828)
  Bottom Layer w0.508: Q10.3@4.064,14.816 v1(4.064,15.875) ; R22.1@13.335,16.129 13.462,16.002 v1(13.462,14.478) ; R13.1@13.97,20.828 v1(15.494,20.828)
NetR4_1: R4.1 U1.7 | length 9.6
  Bottom Layer w0.508: R4.1@28.575,34.722 29.439,33.858 29.439,31.344 30.277,30.505 30.277,29.032 31.648,27.661 U1.7@32.88,27.661
NetR7_1: R7.1 R58.2 | length 3
  Bottom Layer w0.508: R58.2@38.255,31.14 41.201,31.14 R7.1@41.25,31.189
NetR9_2: R9.2 U1.5 | length 2.9
  Bottom Layer w0.381: 32.766,31.191 32.766,30.315 U1.5@32.88,30.201
  Bottom Layer w0.762: R9.2@32.639,32.969 32.766,32.842 32.766,31.191
NetR34_2: R34.2 U2.2 | length 20.6
  Bottom Layer w0.254: R34.2@11.049,10.287 11.195,10.433 27.686,10.433 27.696,10.423 29.811,10.423 30.413,11.026 U2.2@31.339,11.026
NetR36_2: R36.2 U2.3 | length 21.3
  Bottom Layer w0.254: R36.2@11.176,12.573 11.176,12.37 12.659,10.887 29.632,10.887 30.422,11.676 U2.3@31.339,11.676
NetR41_1: R41.1 U2.28 | length 13.9
  Bottom Layer w0.203: U2.28@39.263,16.881 37.436,16.881 36.611,16.056 36.611,9.169 37.246,8.534 38.024,8.534 39.497,7.061 R41.1@39.726,7.061
NetR42_1: R42.1 U2.27 | length 13.4
  Bottom Layer w0.203: R42.1@37.465,7.061 37.186,7.061 36.208,8.039 36.208,16.223 37.516,17.531 U2.27@39.263,17.531
NetR43_1: R43.1 U2.26 | length 13.8
  Bottom Layer w0.203: R43.1@35.154,7.061 35.23,7.137 35.23,8.179 35.804,8.753 35.804,16.39 37.596,18.181 U2.26@39.263,18.181
NetR44_1: R44.1 U2.25 | length 15.5
  Bottom Layer w0.203: R44.1@32.868,7.036 33.096,7.036 35.401,9.341 35.401,16.557 37.676,18.832 U2.25@39.263,18.832
NetR45_1: R45.1 U2.24 | length 17.7
  Bottom Layer w0.203: R45.1@30.607,7.061 30.912,7.061 32.08,8.23 33.235,8.23 34.998,9.993 34.998,16.724 37.756,19.482 U2.24@39.266,19.482
NetR47_1: R47.1 U2.23 | length 20.4
  Bottom Layer w0.203: R47.1@28.169,7.036 R47.1@28.321,7.036 ; R47.1@28.346,7.036 29.308,7.998 31.278,7.998 31.913,8.633 33.068,8.633 34.595,10.16 34.595,16.891 37.836,20.132 U2.23@39.266,20.132
NetR48_2: R48.2 U2.16 | length 7.3
  Bottom Layer w0.381: U2.16@31.341,20.13 32.525,20.13 32.893,20.498 32.893,20.625
  Bottom Layer w0.508: R48.2@29.718,24.155 30.667,23.206 31.734,23.206 32.893,22.047 32.893,20.625
NetR49_2: R49.2 U2.20 | length 7.3
  Bottom Layer w0.381: 37.922,22.073 39.256,22.073 U2.20@39.266,22.083
  Bottom Layer w0.508: R49.2@33.731,24.46 33.731,23.19 34.849,22.073 37.922,22.073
